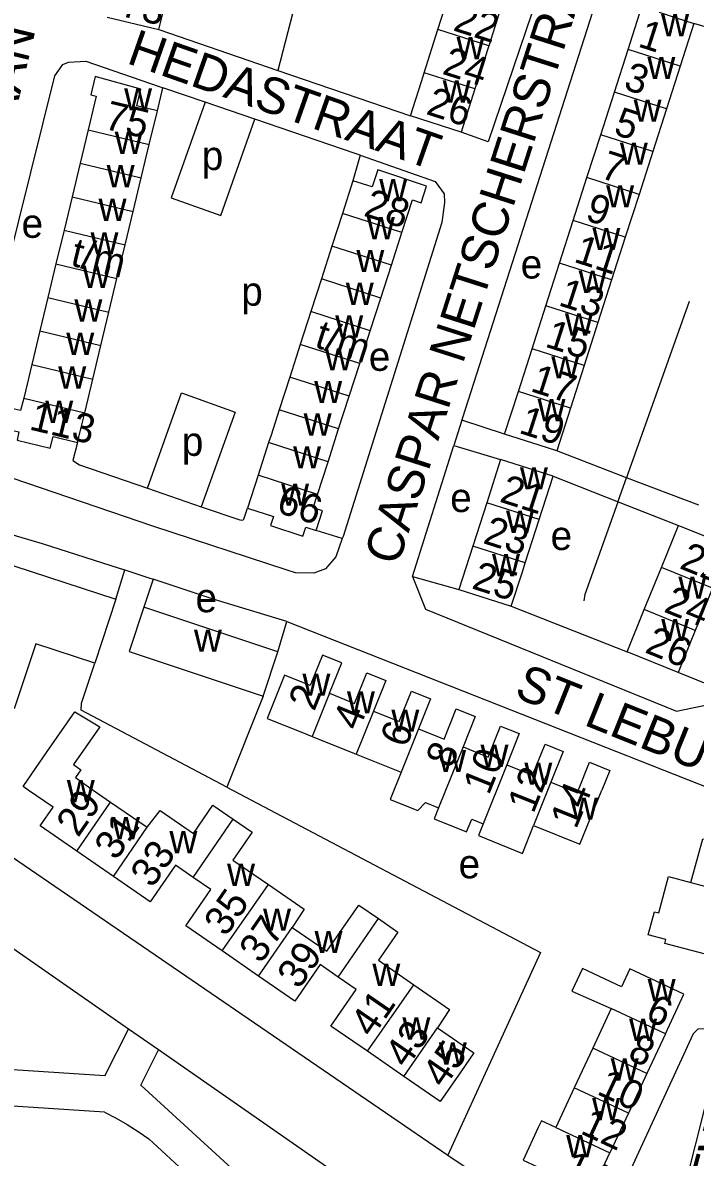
# Model space of a CAD drawing. Extents: x 162804 to 165059, y 381530 to 382901.
# Drawn here: x 163167.6 to 163260.6, y 381949.2 to 382106.1 of the extents above; entities that cross this region are included whole.
import ezdxf

# ---------------------------------------------------------------- set-up
doc = ezdxf.new("R2010")
doc.units = 0
for name, color, linetype in [('BLT_Basislijn', 7, 'Continuous'), ('BLT_Bebouwing', 7, 'Continuous'), ('BLT_Centroide', 7, 'Continuous'), ('BLT_Huisnummer', 7, 'Continuous'), ('BLT_Huisnummer_ tussenligend', 7, 'Continuous'), ('BLT_Huisnummer_reeks', 7, 'Continuous'), ('BLT_Onderverdeling_panden', 7, 'Continuous'), ('BLT_Straatnaam', 7, 'Continuous')]:
    doc.layers.add(name, color=color, linetype=linetype)

msp = doc.modelspace()

# ---------------------------------------------------------------- linework, layer by layer
at = {"layer": 'BLT_Basislijn'}
for p, q in [((163186.43, 382105.15), (163202.88, 382099.5)), ((163202.88, 382099.5), (163221.21, 382093.21)), ((163186.22, 382093.92), (163186.98, 382097.11)), ((163214.26, 382087.77), (163213.27, 382084.24)), ((163228.33, 382051.13), (163227.22, 382047.63)), ((163234.24, 382049.2), (163228.33, 382051.13)), ((163227.22, 382047.63), (163233.69, 382045.72)), ((163251.09, 382043.19), (163241.44, 382046.89)), ((163240.94, 382043.39), (163249.94, 382039.87)), ((163261.08, 382039.37), (163251.09, 382043.19)), ((163249.94, 382039.87), (163258.29, 382036.6)), ((163211.8, 382034.76), (163208.17, 382035.91)), ((163180.49, 382026.38), (163181.72, 382030.43)), ((163185.65, 382029.15), (163184.35, 382025.28)), ((163221.52, 382029.52), (163227.92, 382027.74)), ((163235.17, 382025.41), (163251.18, 382019.13)), ((163202.9, 382019.11), (163204.13, 382023.3)), ((163263.5, 382014.14), (163258.24, 382016.26)), ((163200.87, 382013), (163195.84, 382000.4)), ((163182.22, 381966.95), (163152.26, 381987.77)), ((163178.98, 381960.46), (163182.22, 381966.95)), ((163186.37, 381964.07), (163182.22, 381966.95)), ((163183.92, 381959.18), (163186.37, 381964.07)), ((163254.03, 381917.05), (163186.37, 381964.07)), ((163178.98, 381960.46), (163158.11, 381961.82)), ((163183.92, 381959.18), (163240.8, 381907.34)), ((163178.93, 381955.45), (163157.66, 381956.84)), ((163185.03, 381951.75), (163239.09, 381902.14))]:
    msp.add_line(p, q, dxfattribs=at)
for points in [[(163214.96, 382143.64), (163214.64, 382143.13), (163205.97, 382111.5), (163202.88, 382099.5)], [(163350, 382099.73), (163300, 382120.36), (163263.12, 382135.5), (163261.91, 382135.74), (163257.79, 382135.78), (163254.65, 382134.65), (163252.36, 382132.68), (163250.88, 382131.03), (163241.51, 382117.79), (163231.95, 382089.64), (163228.22, 382090.96)], [(163247.12, 382109.91), (163228.44, 382051.49), (163228.33, 382051.13)], [(163263.54, 382077.66), (163272.27, 382102.55), (163260.42, 382106.01)], [(163160.19, 382051.24), (163160.35, 382051.77), (163172.05, 382098.78), (163173.14, 382100.32), (163173.93, 382100.67), (163176.32, 382100.8), (163186.47, 382097.29), (163186.98, 382097.11)], [(163192.83, 382095.11), (163186.98, 382097.11)], [(163192.83, 382095.11), (163188.15, 382081.87), (163194.98, 382079.45), (163199.69, 382092.76)], [(163199.69, 382092.76), (163192.83, 382095.11)], [(163214.26, 382087.77), (163213.58, 382088.01), (163199.69, 382092.76)], [(163214.26, 382087.77), (163224.62, 382084.13), (163225.89, 382082.43), (163225.94, 382081.24), (163225.58, 382078.46), (163211.9, 382035.05), (163211.8, 382034.76)], [(163259.78, 382067.55), (163251.28, 382043.72), (163251.09, 382043.19)], [(163184.84, 382041.73), (163189.58, 382054.91), (163196.97, 382052.26), (163192.27, 382039.18)], [(163211.8, 382034.76), (163210.88, 382032.25), (163209.48, 382030.58), (163207.86, 382029.98), (163205.33, 382030.03), (163204.16, 382030.4), (163185.58, 382036.47), (163162.33, 382044.43), (163159.79, 382046.61), (163159.78, 382049.85), (163160.19, 382051.24)], [(163175.2, 382048.08), (163174.53, 382045.55), (163175.46, 382044.95), (163184.84, 382041.73)], [(163221.52, 382029.52), (163227.19, 382047.52), (163227.22, 382047.63)], [(163249.94, 382039.87), (163250.01, 382040.08), (163251.09, 382043.19)], [(163184.84, 382041.73), (163192.27, 382039.18)], [(163192.27, 382039.18), (163197.61, 382037.35), (163198.03, 382037.3), (163198.19, 382037.46), (163198.7, 382038.99)], [(163245.25, 382026.16), (163245.4, 382027.1), (163249.94, 382039.87)], [(163145.62, 382004.79), (163143.27, 382006.86), (163142.81, 382007.62), (163142.4, 382008.87), (163142.53, 382011.16), (163151.68, 382034.27), (163152.64, 382035.87), (163153.2, 382036.38), (163155.67, 382037.77), (163157.88, 382037.75), (163170.3, 382034.11), (163180.94, 382030.69), (163181.72, 382030.43)], [(163181.72, 382030.43), (163185.04, 382029.35), (163185.65, 382029.15)], [(163204.13, 382023.3), (163193.94, 382026.37), (163185.65, 382029.15)], [(163221.52, 382029.52), (163223.28, 382025.02), (163257.99, 382010.91), (163262.65, 382011.86), (163263.5, 382014.14)], [(163204.13, 382023.3), (163270.85, 381996.99), (163269.45, 381991.14)], [(163195.84, 382000.4), (163175.69, 382011.02), (163175.74, 382012.03), (163177.59, 382017.54)], [(163145.62, 382004.79), (163166.07, 381990.82), (163226.4, 381949.49)], [(163195.84, 382000.4), (163239.2, 381977.54), (163226.4, 381949.49)], [(163263.43, 381966.84), (163262.51, 381966.98), (163260.96, 381966.92), (163260.32, 381966.28), (163246.31, 381935.84)], [(163263.43, 381966.84), (163264.37, 381966.69), (163264.02, 381964.44), (163257.21, 381937.51), (163255.95, 381935.36), (163255.35, 381934.85), (163252.41, 381933.69), (163249.35, 381934.09), (163248.43, 381934.43), (163246.31, 381935.84)], [(163178.93, 381955.45), (163180.52, 381954.63), (163182.07, 381953.73), (163183.58, 381952.77), (163185.03, 381951.75)], [(163226.4, 381949.49), (163234.92, 381943.81), (163246.31, 381935.84)]]:
    msp.add_lwpolyline(points, dxfattribs=at)
at = {"layer": 'BLT_Bebouwing'}
for p, q in [((163186.43, 382105.15), (163187.92, 382111.24)), ((163225.03, 382105.17), (163226.95, 382111.15)), ((163233.96, 382108.91), (163232.05, 382102.93)), ((163251.32, 382102.42), (163253.22, 382108.33)), ((163179.29, 382106.88), (163186.43, 382105.15)), ((163223.12, 382099.19), (163225.03, 382105.17)), ((163260.42, 382106.01), (163258.53, 382100.11)), ((163232.05, 382102.93), (163230.14, 382096.95)), ((163249.42, 382096.51), (163251.32, 382102.42)), ((163258.53, 382100.11), (163256.63, 382094.2)), ((163230.14, 382096.95), (163228.22, 382090.96)), ((163247.53, 382090.6), (163249.42, 382096.51)), ((163256.63, 382094.2), (163254.73, 382088.28)), ((163185.1, 382089.28), (163186.22, 382093.92)), ((163228.22, 382090.96), (163221.21, 382093.21)), ((163176.66, 382091.31), (163175.55, 382086.67)), ((163183.99, 382084.64), (163185.1, 382089.28)), ((163245.63, 382084.68), (163247.53, 382090.6)), ((163254.73, 382088.28), (163252.83, 382082.37)), ((163175.55, 382086.67), (163174.43, 382082.03)), ((163182.87, 382080), (163183.99, 382084.64)), ((163243.73, 382078.77), (163245.63, 382084.68)), ((163213.27, 382084.24), (163211.81, 382079.73)), ((163174.43, 382082.03), (163173.32, 382077.4)), ((163252.83, 382082.37), (163250.93, 382076.46)), ((163181.76, 382075.37), (163182.87, 382080)), ((163211.81, 382079.73), (163210.36, 382075.2)), ((163241.83, 382072.86), (163243.73, 382078.77)), ((163173.32, 382077.4), (163172.2, 382072.76)), ((163218.58, 382072.56), (163220.03, 382077.08)), ((163180.64, 382070.73), (163181.76, 382075.37)), ((163210.36, 382075.2), (163208.9, 382070.68)), ((163250.93, 382076.46), (163249.04, 382070.54)), ((163172.2, 382072.76), (163171.09, 382068.12)), ((163217.12, 382068.03), (163218.58, 382072.56)), ((163239.93, 382066.94), (163241.83, 382072.86)), ((163179.53, 382066.09), (163180.64, 382070.73)), ((163208.9, 382070.68), (163207.44, 382066.15)), ((163249.04, 382070.54), (163247.14, 382064.63)), ((163171.09, 382068.12), (163169.97, 382063.48)), ((163215.66, 382063.5), (163217.12, 382068.03)), ((163178.41, 382061.45), (163179.53, 382066.09)), ((163207.44, 382066.15), (163205.98, 382061.62)), ((163238.03, 382061.03), (163239.93, 382066.94)), ((163247.14, 382064.63), (163245.24, 382058.72)), ((163169.97, 382063.48), (163168.86, 382058.84)), ((163214.2, 382058.98), (163215.66, 382063.5)), ((163177.3, 382056.81), (163178.41, 382061.45)), ((163205.98, 382061.62), (163204.53, 382057.1)), ((163236.14, 382055.12), (163238.03, 382061.03)), ((163168.86, 382058.84), (163167.74, 382054.21)), ((163212.75, 382054.45), (163214.2, 382058.98)), ((163245.24, 382058.72), (163243.34, 382052.8)), ((163176.18, 382052.18), (163177.3, 382056.81)), ((163204.53, 382057.1), (163203.07, 382052.57)), ((163234.24, 382049.2), (163236.14, 382055.12)), ((163211.29, 382049.93), (163212.75, 382054.45)), ((163175.65, 382049.97), (163176.18, 382052.18)), ((163203.07, 382052.57), (163201.94, 382049.06)), ((163243.34, 382052.8), (163241.44, 382046.89)), ((163175.2, 382048.08), (163175.65, 382049.97)), ((163201.94, 382049.06), (163201.61, 382048.05)), ((163209.83, 382045.4), (163211.29, 382049.93)), ((163201.61, 382048.05), (163200.15, 382043.52)), ((163208.38, 382040.87), (163209.83, 382045.4)), ((163233.69, 382045.72), (163231.77, 382039.73)), ((163200.15, 382043.52), (163198.7, 382038.99)), ((163239.02, 382037.4), (163240.94, 382043.39)), ((163231.77, 382039.73), (163229.84, 382033.73)), ((163237.1, 382031.41), (163239.02, 382037.4)), ((163255.92, 382030.78), (163258.29, 382036.6)), ((163229.84, 382033.73), (163227.92, 382027.74)), ((163163.06, 382032.1), (163180.49, 382026.38)), ((163253.55, 382024.95), (163255.92, 382030.78)), ((163227.92, 382027.74), (163235.17, 382025.41)), ((163262.97, 382027.91), (163260.6, 382022.08)), ((163180.49, 382026.38), (163177.59, 382017.54)), ((163202.9, 382019.11), (163184.35, 382025.28)), ((163260.6, 382022.08), (163258.24, 382016.26)), ((163200.87, 382013), (163202.9, 382019.11)), ((163258.24, 382016.26), (163251.18, 382019.13)), ((163207.62, 382007.41), (163213.73, 382004.95)), ((163213.73, 382004.95), (163219.92, 382002.46)), ((163177.35, 382000), (163179.76, 381998.34)), ((163240.64, 382001.09), (163243.35, 382000)), ((163179.76, 381998.34), (163184.83, 381994.84)), ((163180.16, 381988.06), (163175.08, 381991.56)), ((163200.21, 381974.27), (163195.18, 381977.74)), ((163248.99, 381969.8), (163246.44, 381964.31)), ((163256.49, 381966.3), (163253.93, 381960.82)), ((163220.31, 381960.39), (163215.27, 381963.87)), ((163246.44, 381964.31), (163243.88, 381958.83)), ((163253.93, 381960.82), (163251.37, 381955.33)), ((163243.88, 381958.83), (163241.32, 381953.34)), ((163251.37, 381955.33), (163248.81, 381949.85))]:
    msp.add_line(p, q, dxfattribs=at)
for points in [[(163253.22, 382108.33), (163257.98, 382106.8), (163260.42, 382106.01)], [(163221.21, 382093.21), (163222.73, 382097.97), (163223.12, 382099.19)], [(163186.22, 382093.92), (163183.4, 382094.6), (163183.96, 382096.93), (163177.64, 382098.68), (163177.03, 382096.13), (163177.78, 382095.95), (163176.66, 382091.31)], [(163220.03, 382077.08), (163221.49, 382081.6), (163222.7, 382081.21), (163223.43, 382083.49), (163216.7, 382085.76), (163215.93, 382083.39), (163213.27, 382084.24)], [(163167.74, 382054.21), (163167.32, 382052.46), (163166.07, 382052.76), (163165.39, 382049.92)], [(163165.39, 382049.92), (163167.09, 382049.51), (163166.82, 382048.39), (163171.41, 382047.29), (163171.8, 382048.89), (163175.2, 382048.08)], [(163241.44, 382046.89), (163239, 382047.68), (163234.24, 382049.2)], [(163240.94, 382043.39), (163238.45, 382044.19), (163233.69, 382045.72)], [(163208.17, 382035.91), (163209.04, 382038.62), (163207.78, 382039.03), (163208.38, 382040.87)], [(163198.7, 382038.99), (163202.29, 382037.84), (163201.88, 382036.57), (163206.36, 382035.12), (163206.76, 382036.36), (163208.17, 382035.91)], [(163258.29, 382036.6), (163260.71, 382035.62), (163265.34, 382033.73)], [(163177.59, 382017.54), (163169.4, 382020.23), (163166.44, 382011.21), (163164.92, 382011.71), (163164.43, 382011.11), (163161.72, 382007.59), (163158.19, 382010.3), (163159.52, 382014.36), (163156.25, 382015.44), (163158.92, 382023.55), (163158.7, 382023.62), (163159.71, 382026.7), (163161.14, 382026.23), (163163.06, 382032.1)], [(163235.17, 382025.41), (163236.7, 382030.17), (163237.1, 382031.41)], [(163184.35, 382025.28), (163182.32, 382019.17), (163200.87, 382013)], [(163251.18, 382019.13), (163253.55, 382024.95)], [(163210.02, 382013.38), (163211.71, 382017.59), (163209.06, 382018.65), (163207.37, 382014.45), (163203.82, 382015.87), (163201.43, 382009.91), (163206.07, 382008.04), (163207.62, 382007.41)], [(163210.02, 382013.38), (163213.5, 382011.98), (163215.19, 382016.21), (163217.82, 382015.15), (163216.12, 382010.91)], [(163216.12, 382010.91), (163219.68, 382009.48), (163221.37, 382013.69), (163224, 382012.63), (163222.33, 382008.47)], [(163222.33, 382008.47), (163225.88, 382007.04), (163227.56, 382011.23), (163230.18, 382010.17), (163228.49, 382005.95)], [(163168.38, 382000), (163167.65, 382000.49), (163170.5, 382004.6), (163171.32, 382005.78), (163174.79, 382010.79), (163178.25, 382008.76), (163174.61, 382003.51), (163175.65, 382002.8), (163174.9, 382001.71), (163177.35, 382000)], [(163228.49, 382005.95), (163231.96, 382004.56), (163233.68, 382008.84), (163236.27, 382007.8), (163234.55, 382003.5)], [(163234.55, 382003.5), (163238.11, 382002.07), (163239.83, 382006.35), (163242.35, 382005.34), (163240.64, 382001.09)], [(163244.46, 382000.01), (163246, 382003.83), (163248.78, 382002.71), (163247.69, 382000)], [(163219.92, 382002.46), (163218.4, 381998.69), (163222.22, 381997.15), (163223.31, 381998.26), (163225.11, 381997.54)], [(163175.08, 381991.56), (163170.01, 381995.05), (163171.8, 381997.65), (163168.38, 382000)], [(163238.24, 381995.1), (163244.64, 381992.52), (163247.69, 382000)], [(163243.35, 382000), (163244.31, 381999.61), (163244.46, 382000.01)], [(163184.83, 381994.84), (163186.62, 381997.18), (163191.21, 381994.01), (163193.9, 381997.91), (163196.71, 381995.97)], [(163225.11, 381997.54), (163224.51, 381996.03), (163228.99, 381994.23), (163229.69, 381995.97), (163231.27, 381995.33)], [(163196.71, 381995.97), (163199.32, 381994.17), (163196.66, 381990.31), (163201.57, 381986.93)], [(163231.27, 381995.33), (163230.61, 381993.69), (163236.7, 381991.24), (163238.24, 381995.1)], [(163260.01, 381987.22), (163261.63, 381993.24), (163269.45, 381991.14)], [(163191.16, 381987.92), (163188.71, 381989.61), (163185.23, 381984.56), (163180.16, 381988.06)], [(163195.18, 381977.74), (163190.14, 381981.21), (163193.61, 381986.24), (163191.16, 381987.92)], [(163266.2, 381979.05), (163262.56, 381980.03), (163261.83, 381977.33), (163256.38, 381978.79), (163256.52, 381979.32), (163254.11, 381979.97), (163254.97, 381983.17), (163255.57, 381983.01), (163256.92, 381988.05), (163260.01, 381987.22)], [(163201.57, 381986.93), (163206.52, 381983.52), (163204.86, 381981.01)], [(163204.86, 381981.01), (163209.66, 381977.7), (163214.07, 381984.09), (163216.8, 381982.21)], [(163216.8, 381982.21), (163219.48, 381980.36), (163216.79, 381976.45), (163221.68, 381973.08)], [(163211.23, 381974.13), (163208.73, 381975.85), (163205.24, 381970.8), (163200.21, 381974.27)], [(163256.49, 381966.3), (163259.04, 381971.79), (163254.51, 381973.9), (163251.55, 381975.28), (163250.39, 381972.79), (163245, 381975.3), (163243.55, 381972.2), (163248.99, 381969.8)], [(163215.27, 381963.87), (163210.23, 381967.34), (163213.73, 381972.41), (163211.23, 381974.13)], [(163221.68, 381973.08), (163226.64, 381969.66), (163224.94, 381967.11)], [(163224.94, 381967.11), (163229.98, 381963.64), (163228.19, 381961.04), (163225.35, 381956.92), (163220.31, 381960.39)], [(163241.32, 381953.34), (163239.33, 381954.27), (163238.9, 381953.35), (163236.79, 381948.82), (163238.8, 381947.88), (163238.71, 381947.68), (163246.18, 381944.2), (163248.81, 381949.85)]]:
    msp.add_lwpolyline(points, dxfattribs=at)
at = {"layer": 'BLT_Onderverdeling_panden'}
for p, q in [((163232.05, 382102.93), (163225.03, 382105.17)), ((163258.53, 382100.11), (163251.32, 382102.42)), ((163230.14, 382096.95), (163223.12, 382099.19)), ((163256.63, 382094.2), (163249.42, 382096.51)), ((163176.66, 382091.31), (163185.1, 382089.28)), ((163254.73, 382088.28), (163247.53, 382090.6)), ((163175.55, 382086.67), (163183.99, 382084.64)), ((163252.83, 382082.37), (163245.63, 382084.68)), ((163174.43, 382082.03), (163182.87, 382080)), ((163220.03, 382077.08), (163211.81, 382079.73)), ((163250.93, 382076.46), (163243.73, 382078.77)), ((163173.32, 382077.4), (163181.76, 382075.37)), ((163218.58, 382072.56), (163210.36, 382075.2)), ((163172.2, 382072.76), (163180.64, 382070.73)), ((163249.04, 382070.54), (163241.83, 382072.86)), ((163217.12, 382068.03), (163208.9, 382070.68)), ((163171.09, 382068.12), (163179.53, 382066.09)), ((163215.66, 382063.5), (163207.44, 382066.15)), ((163247.14, 382064.63), (163239.93, 382066.94)), ((163169.97, 382063.48), (163178.41, 382061.45)), ((163214.2, 382058.98), (163205.98, 382061.62)), ((163245.24, 382058.72), (163238.03, 382061.03)), ((163168.86, 382058.84), (163177.3, 382056.81)), ((163212.75, 382054.45), (163204.53, 382057.1)), ((163243.34, 382052.8), (163236.14, 382055.12)), ((163167.74, 382054.21), (163176.18, 382052.18)), ((163211.29, 382049.93), (163203.07, 382052.57)), ((163209.83, 382045.4), (163201.61, 382048.05)), ((163208.38, 382040.87), (163200.15, 382043.52)), ((163239.02, 382037.4), (163231.77, 382039.73)), ((163237.1, 382031.41), (163229.84, 382033.73)), ((163262.97, 382027.91), (163255.92, 382030.78)), ((163260.6, 382022.08), (163253.55, 382024.95)), ((163210.02, 382013.38), (163207.62, 382007.41)), ((163216.12, 382010.91), (163213.73, 382004.95)), ((163222.33, 382008.47), (163219.92, 382002.46)), ((163228.49, 382005.95), (163225.11, 381997.54)), ((163234.55, 382003.5), (163231.27, 381995.33)), ((163240.64, 382001.09), (163238.24, 381995.1)), ((163175.08, 381991.56), (163179.76, 381998.34)), ((163191.16, 381987.92), (163196.71, 381995.97)), ((163180.16, 381988.06), (163184.83, 381994.84)), ((163195.18, 381977.74), (163201.57, 381986.93)), ((163260.01, 381987.22), (163267.83, 381985.11)), ((163200.21, 381974.27), (163204.86, 381981.01)), ((163211.23, 381974.13), (163216.8, 381982.21)), ((163215.27, 381963.87), (163221.68, 381973.08)), ((163256.49, 381966.3), (163248.99, 381969.8)), ((163220.31, 381960.39), (163224.94, 381967.11)), ((163253.93, 381960.82), (163246.44, 381964.31)), ((163251.37, 381955.33), (163243.88, 381958.83)), ((163241.32, 381953.34), (163248.81, 381949.85))]:
    msp.add_line(p, q, dxfattribs=at)

# ---------------------------------------------------------------- texts
at = {"layer": 'BLT_Centroide'}
for s, p in [('w', (163255.88, 382104.22)), ('w', (163227.59, 382101.06)), ('w', (163253.98, 382098.31)), ('w', (163225.68, 382095.06)), ('w', (163181.63, 382093.97)), ('w', (163252.08, 382092.41)), ('w', (163180.33, 382087.97)), ('w', (163250.18, 382086.47)), ('p', (163192.36, 382085.74)), ('w', (163179.21, 382083.34)), ('w', (163216.9, 382081.41)), ('w', (163248.28, 382080.56)), ('w', (163178.09, 382078.69)), ('e', (163167.45, 382076.36)), ('w', (163215.2, 382076.16)), ('w', (163176.98, 382074.06)), ('w', (163246.38, 382074.66)), ('w', (163213.74, 382071.62)), ('e', (163236.47, 382070.73)), ('w', (163175.87, 382069.44)), ('w', (163244.48, 382068.75)), ('p', (163197.83, 382066.97)), ('w', (163212.28, 382067.09)), ('w', (163174.75, 382064.78)), ('w', (163242.59, 382062.84)), ('w', (163210.82, 382062.56)), ('w', (163173.63, 382060.16)), ('w', (163209.37, 382058.03)), ('e', (163215.46, 382057.96)), ('w', (163240.69, 382056.91)), ('w', (163172.52, 382055.5)), ('w', (163207.91, 382053.5)), ('w', (163170.72, 382050.75)), ('w', (163238.79, 382051)), ('w', (163206.45, 382049)), ('p', (163189.61, 382046.21)), ('w', (163204.99, 382044.47)), ('w', (163236.36, 382041.56)), ('w', (163203.34, 382039.31)), ('e', (163226.72, 382038.44)), ('w', (163234.44, 382035.56)), ('e', (163240.6, 382033.19)), ('w', (163232.5, 382029.56)), ('w', (163258.27, 382026.44)), ('e', (163191.5, 382024.58)), ('w', (163255.89, 382020.59)), ('w', (163191.28, 382019.12)), ('w', (163206.28, 382013.03)), ('w', (163212.44, 382010.59)), ('w', (163218.58, 382008.06)), ('w', (163230.91, 382003.19)), ('w', (163225.05, 382002.47)), ('w', (163236.97, 382000.72)), ('w', (163173.7, 381998.31)), ('w', (163243.28, 381995.88)), ('w', (163179.95, 381993.19)), ('w', (163187.89, 381991.25)), ('e', (163227.88, 381987.79)), ('w', (163195.86, 381986.73)), ('w', (163200.84, 381980.53)), ('w', (163207.96, 381977.44)), ('w', (163215.95, 381972.92)), ('w', (163254.02, 381970.78)), ('w', (163220.11, 381965.48)), ('w', (163251.46, 381965.31)), ('w', (163225.14, 381962.02)), ('w', (163248.91, 381959.81)), ('w', (163246.34, 381954.34)), ('w', (163242.76, 381949.22))]:
    msp.add_text(s, height=4, dxfattribs=at).set_placement(p)
at = {"layer": 'BLT_Huisnummer'}
for s, rotation, p in [('73', 346.3363, (163180.94, 382107.09)), ('22', 342.261, (163226.97, 382105.08)), ('1', 342.1968, (163252.53, 382102.85)), ('26', 342.2586, (163223.23, 382093.51)), ('5', 342.2017, (163249.16, 382090.72)), ('9', 342.1994, (163245.24, 382078.85)), ('13', 342.1971, (163241.54, 382067.07)), ('19', 342.2003, (163236.06, 382049.42)), ('21', 342.2003, (163233.4, 382039.91)), ('22', 337.8703, (163258.27, 382030.71)), ('25', 342.2003, (163229.54, 382027.92)), ('26', 337.8633, (163253.48, 382019.08)), ('2', 68.1258, (163207.92, 382010.78)), ('6', 68.123, (163220.6, 382005.69)), ('10', 68.1274, (163232.06, 381999.18)), ('14', 67.9496, (163244.13, 381994.47)), ('29', 55.4284, (163175.26, 381993.33)), ('33', 55.426, (163185.52, 381986.31)), ('35', 55.4288, (163195.69, 381979.58)), ('39', 55.4296, (163205.81, 381972.32)), ('41', 55.4336, (163215.94, 381965.61)), ('6', 335.0007, (163253.51, 381968.32)), ('45', 55.4266, (163225.86, 381958.62)), ('10', 334.9978, (163246.84, 381958.01)), ('14', 334.9995, (163242.08, 381946.66))]:
    msp.add_text(s, height=4, rotation=rotation, dxfattribs=at).set_placement(p)
at = {"layer": 'BLT_Huisnummer_ tussenligend'}
for s, rotation, p in [('24', 342.261, (163225.46, 382099.07)), ('3', 342.1968, (163250.53, 382096.97)), ('7', 342.2017, (163247.29, 382084.71)), ('11', 342.1994, (163243.67, 382073.07)), ('15', 342.1971, (163239.68, 382061.35)), ('17', 342.1971, (163237.66, 382055.19)), ('23', 342.2003, (163231.11, 382034.18)), ('24', 337.8703, (163256.11, 382024.7)), ('4', 68.1258, (163214.07, 382008.05)), ('8', 68.123, (163226.9, 382002.84)), ('12', 68.1274, (163238.22, 381996.62)), ('31', 55.4284, (163180.53, 381990.12)), ('37', 55.4288, (163200.55, 381975.85)), ('43', 55.4336, (163220.69, 381961.38)), ('8', 335.0007, (163251.08, 381962.87)), ('12', 334.9978, (163244.56, 381952.57))]:
    msp.add_text(s, height=4, rotation=rotation, dxfattribs=at).set_placement(p)
at = {"layer": 'BLT_Huisnummer_reeks'}
for s, rotation, p in [('75', 346.4809, (163178.71, 382091.48)), ('28', 342.1525, (163214.61, 382079.44)), ('t/m', 346.4809, (163174.07, 382072.55)), ('t/m', 342.1525, (163207.8, 382061.29)), ('113', 346.4756, (163168.37, 382049.89)), ('66', 342.1685, (163202.52, 382038.46))]:
    msp.add_text(s, height=4, rotation=rotation, dxfattribs=at).set_placement(p)
at = {"layer": 'BLT_Straatnaam'}
for s, height, rotation, p in [('CASPAR NETSCHERSTRAAT', 4.9999, 72.2045, (163219.49, 382030.87)), ('MOREELSELAAN', 5, 76.4507, (163156.61, 382052.05)), ('HEDASTRAAT', 5, 340.6685, (163181.82, 382100.56)), ('ST LEBUINUSLAAN', 5, 338.104, (163235.4, 382012.93)), ('ST EWALDSTRAAT', 5, 75.0544, (163261.9, 381934.5))]:
    msp.add_text(s, height=height, rotation=rotation, dxfattribs=at).set_placement(p)

doc.saveas('drawing.dxf')
